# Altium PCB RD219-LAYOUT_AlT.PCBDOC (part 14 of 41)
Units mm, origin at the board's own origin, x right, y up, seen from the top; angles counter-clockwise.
Board outline 209.75 x 159.97 mm, 2 copper layers (TOP, BOTTOM), stack 0 mm thick; 398 components, 199 nets, 1469 pads, 0 vias.
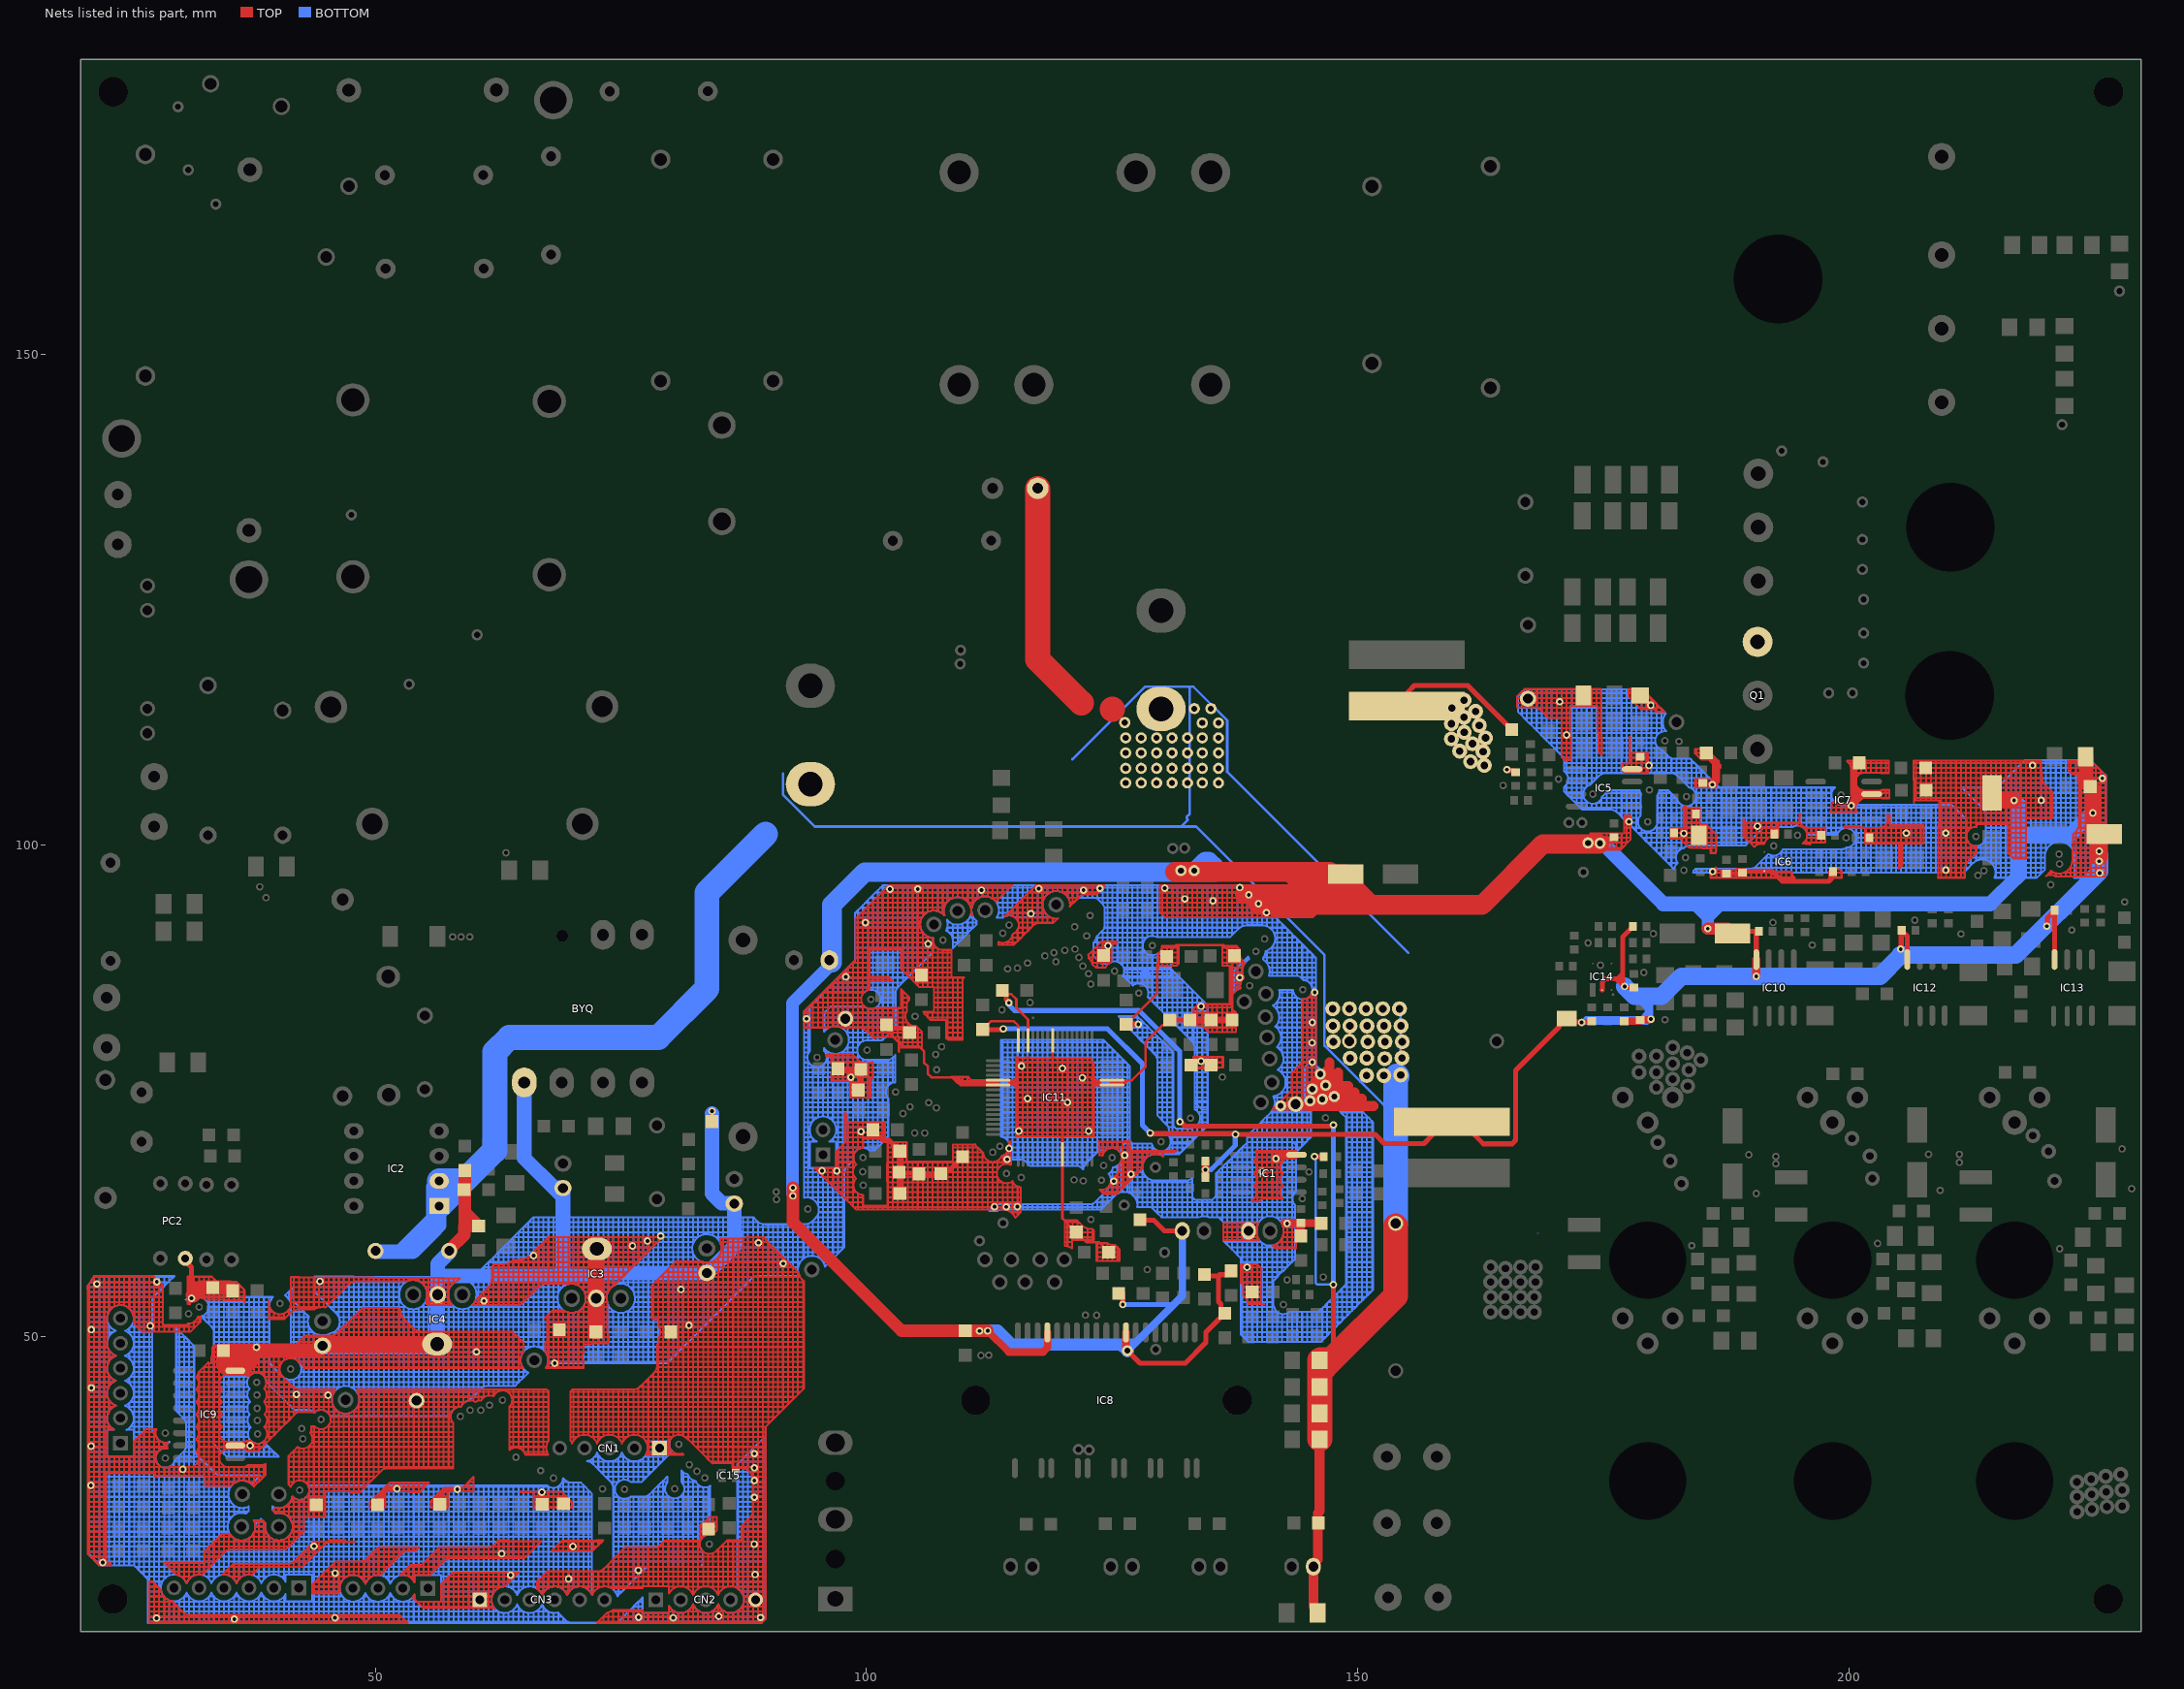
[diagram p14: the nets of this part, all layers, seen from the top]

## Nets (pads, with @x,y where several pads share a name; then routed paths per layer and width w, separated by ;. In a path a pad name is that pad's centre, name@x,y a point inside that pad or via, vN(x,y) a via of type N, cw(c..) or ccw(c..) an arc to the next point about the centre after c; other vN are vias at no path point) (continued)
GND: (continued)
  TOP w0.203: 113.345,67.931 ccw(c112.851,68.781) 113.684,68.26 ; 113.345,94.45 113.345,94.676 ; 113.345,94.45 113.571,94.676 ; 113.345,94.676 113.345,95.184 ; 113.345,94.676 113.571,94.676 ; 113.345,95.184 113.345,95.692 ; 113.345,95.184 113.853,95.184 ; 113.345,95.692 113.345,95.946 ; 113.345,95.692 113.853,95.692 ; 113.345,95.946 113.853,95.946 ; 113.454,90.104 113.454,89.885 113.853,89.885 ; 113.454,90.104 113.619,90.104 ; 113.454,90.104 113.454,90.163 ; 113.454,90.163 ccw(c113.863,91.056) 113.619,90.104 ; 113.571,94.676 113.853,94.958 ; 113.619,90.104 ccw(c113.863,91.056) 113.846,90.073 ccw(c113.863,91.056) 113.853,90.073 ; 113.684,68.26 113.853,68.26 ; 113.828,65.72 ccw(c114.245,66.61) 113.853,65.709 ; 113.853,62.932 113.853,63.18 ; 113.853,62.932 113.895,62.932 ; 113.853,63.18 113.853,63.688 ; 113.853,63.18 pad.@114.361,63.18 ; 113.853,63.688 113.853,64.196 ; 113.853,63.688 114.361,63.688 ; 113.853,64.196 113.853,64.704 ; 113.853,64.196 114.361,64.196 ; 113.853,64.704 113.853,65.212 ; 113.853,64.704 114.361,64.704 ; 113.853,65.212 114.361,65.212 ; 113.853,65.212 113.853,65.709 ; 113.853,65.709 ccw(c114.245,66.61) 114.361,65.634 ; 113.853,67.511 cw(c114.245,66.61) 114.361,67.586 ; 113.853,67.511 113.853,67.752 ; 113.853,67.752 pad.@114.361,67.752 ; 113.853,67.752 113.853,68.26 ; 113.853,68.26 pad.@114.361,68.26 ; 113.853,68.26 113.853,68.436 ; 113.853,68.436 ccw(c113.576,69.379) 114.346,68.768 ; 113.853,89.885 114.361,89.885 ; 113.853,89.885 113.853,90.073 ; 113.853,90.073 ccw(c113.863,91.056) 114.101,90.102 ccw(c113.863,91.056) 114.108,90.104 ; 113.853,94.958 113.853,95.184 ; 113.853,94.958 114.079,95.184 ; 113.853,95.184 113.853,95.692 ; 113.853,95.184 114.079,95.184 ; 113.853,95.692 113.853,95.946 ; 113.853,95.692 114.361,95.692 ; 113.853,95.946 114.361,95.946 ; 113.895,62.932 cw(c113.895,61.581) 114.361,62.85 ; 113.895,62.932 cw(c113.895,61.581) 114.361,62.85 ; 114.079,95.184 114.361,95.466 ; 114.108,90.104 ccw(c113.863,91.056) 114.355,90.205 ccw(c113.863,91.056) 114.361,90.208 ; 114.108,90.104 114.361,90.104 ; 114.346,68.768 ccw(c113.576,69.379) 114.361,68.788 ; 114.346,68.768 114.361,68.768 ; 114.361,62.85 cw(c113.895,61.581) 114.693,62.672 ; 114.361,62.85 cw(c113.895,61.581) 114.693,62.672 ; 114.361,62.85 pad.@114.361,63.18 ; pad.@114.361,63.18 114.869,63.18 ; pad.@114.361,63.18 114.361,63.688 ; 114.361,63.688 114.361,64.196 ; 114.361,63.688 114.869,63.688 ; 114.361,64.196 114.361,64.704 ; 114.361,64.196 114.869,64.196 ; 114.361,64.704 114.361,65.212 ; 114.361,64.704 114.869,64.704 ; 114.361,65.212 114.869,65.212 ; 114.361,65.212 114.361,65.634 ; 114.361,65.634 ccw(c114.245,66.61) 114.661,65.72 ; 114.361,67.586 cw(c114.245,66.61) 114.685,67.488 ; 114.361,67.586 pad.@114.361,67.752 ; pad.@114.361,67.752 114.685,67.752 ; pad.@114.361,67.752 pad.@114.361,68.26 ; pad.@114.361,68.26 114.685,68.26 ; pad.@114.361,68.26 114.361,68.768 ; 114.361,68.768 114.361,68.788 ; 114.361,68.768 114.685,68.768 ; 114.361,68.788 ccw(c113.576,69.379) pad.@114.553,69.276 ; 114.361,89.885 114.869,89.885 ; 114.361,89.885 114.361,90.104 ; 114.361,90.104 114.869,90.104 ; 114.361,90.104 114.361,90.208 ; 114.361,90.208 ccw(c113.863,91.056) 114.739,90.61 ccw(c113.863,91.056) 114.74,90.612 ; 114.361,95.466 114.361,95.692 ; 114.361,95.466 114.841,95.946 114.361,95.946 ; 114.361,95.692 114.361,95.946 ; 114.455,93.152 114.869,93.152 ; 114.455,93.152 114.869,93.566 ; 114.472,69.784 cw(c113.576,69.379) 114.559,69.379 cw(c113.576,69.379) pad.@114.553,69.276 ; 114.472,69.784 114.696,69.784 ; pad.@114.553,69.276 pad.@114.685,69.276 ; 114.661,65.72 ccw(c114.245,66.61) 114.842,65.83 ; 114.661,65.72 114.869,65.72 ; 114.682,75.88 cw(c114.487,76.606) 114.539,75.856 cw(c114.487,75.106) 114.869,75.753 ; 114.682,75.88 ccw(c114.487,76.606) 114.869,75.959 ; 114.682,75.88 114.869,75.88 ; 114.685,67.488 114.685,67.752 ; 114.685,67.752 114.685,68.26 ; 114.685,68.26 114.685,68.768 ; 114.685,68.768 pad.@114.685,69.276 ; pad.@114.685,69.276 114.685,69.656 cw(c115.437,69.656) 114.696,69.784 ; 114.693,62.672 cw(c113.895,61.581) 114.851,62.537 ccw(c113.895,61.581) 114.693,62.672 ; 114.693,62.672 114.869,62.672 ; 114.74,90.612 114.869,90.612 ; 114.842,65.83 ccw(c115.751,66.202) 114.869,65.769 ; 114.869,62.518 cw(c113.9,61.576) 115.117,62.164 ; 114.869,62.518 114.869,62.672 ; 114.869,62.672 114.869,63.18 ; 114.869,62.672 115.377,62.672 ; 114.869,63.18 114.869,63.688 ; 114.869,63.18 pad.@115.377,63.18 ; 114.869,63.688 114.869,64.196 ; 114.869,63.688 115.377,63.688 ; 114.869,64.196 114.869,64.704 ; 114.869,64.196 115.377,64.196 ; 114.869,64.704 114.869,65.212 ; 114.869,64.704 115.377,64.704 ; 114.869,65.212 114.869,65.72 ; 114.869,65.212 115.377,65.212 ; 114.869,65.72 114.895,65.72 ; 114.869,65.72 114.869,65.769 ; 114.869,65.769 ccw(c115.751,66.202) 114.895,65.72 ; 114.869,75.753 cw(c114.487,75.106) 115.028,75.628 cw(c114.487,75.106) 115.03,75.626 cw(c114.487,75.106) 115.189,75.375 cw(c114.487,75.106) 115.19,75.372 ; 114.869,75.753 114.869,75.88 ; 114.869,75.88 115.377,75.88 ; 114.869,75.88 114.869,75.959 ; 114.869,75.959 ccw(c114.487,76.606) 114.874,75.962 ccw(c114.487,76.606) 115.034,76.091 ccw(c114.487,76.606) 115.087,76.154 ccw(c114.487,76.606) 115.206,76.386 ccw(c114.487,76.606) 115.206,76.388 ; 114.869,89.885 115.016,89.885 115.236,90.104 ; 114.869,89.885 114.869,90.104 ; 114.869,90.104 114.869,90.612 ; 114.869,90.104 115.236,90.104 ; 114.869,90.612 115.377,90.612 ; 114.869,90.612 114.869,90.977 ; 114.869,90.977 ccw(c114.506,91.891) 115.111,91.116 ccw(c114.506,91.891) 115.116,91.12 ; 114.869,92.804 cw(c114.506,91.891) 115.137,92.644 ; 114.869,92.804 114.869,93.152 ; 114.869,93.152 114.869,93.566 ; 114.869,93.152 115.377,93.152 ; 114.869,93.566 114.963,93.66 ; 114.963,93.66 115.377,94.074 ; 114.963,93.66 115.377,93.66 ; 115.117,62.164 cw(c113.9,61.576) 115.144,62.106 ; 115.116,91.12 ccw(c114.506,91.891) 115.374,91.429 ccw(c114.506,91.891) 115.377,91.435 ; 115.116,91.12 115.377,91.12 ; 115.137,92.644 cw(c114.506,91.891) 115.374,92.352 cw(c114.506,91.891) 115.377,92.346 ; 115.137,92.644 115.377,92.644 ; 115.144,62.106 115.377,62.339 ; 115.17,78.42 cw(c114.487,78.106) 115.239,78.106 cw(c114.487,78.106) 115.213,77.912 ; 115.17,78.42 115.377,78.42 ; 115.19,75.372 cw(c114.487,75.106) 115.239,75.106 cw(c114.487,75.106) 115.199,74.864 ; 115.19,75.372 115.377,75.372 ; 115.199,73.848 115.377,73.848 ; 115.199,74.864 115.377,74.864 ; 115.201,73.34 115.377,73.34 ; 115.204,72.832 115.377,72.832 ; 115.206,72.324 115.377,72.324 ; 115.206,76.388 115.377,76.388 ; 115.209,71.816 115.377,71.816 ; 115.209,76.896 115.377,76.896 ; 115.211,71.308 115.377,71.308 ; 115.211,77.404 115.377,77.404 ; pad.@115.213,70.8 pad.@115.377,70.8 ; 115.213,77.912 115.377,77.912 ; 115.236,90.104 115.377,90.245 ; 115.377,62.339 115.377,62.672 ; 115.377,62.339 115.708,62.671 115.708,62.672 ; 115.377,62.672 pad.@115.377,63.18 ; 115.377,62.672 115.708,62.672 ; pad.@115.377,63.18 pad.@115.708,63.18 ; pad.@115.377,63.18 115.377,63.688 ; 115.377,63.688 115.377,64.196 ; 115.377,63.688 115.708,63.688 ; 115.377,64.196 115.377,64.704 ; 115.377,64.196 115.708,64.196 ; 115.377,64.704 115.377,65.212 ; 115.377,64.704 115.708,64.704 ; 115.377,65.212 115.708,65.212 ; 115.377,70.405 pad.@115.377,70.8 ; pad.@115.377,70.8 115.377,71.308 ; pad.@115.377,70.8 115.885,70.8 ; 115.377,71.308 115.377,71.816 ; 115.377,71.308 115.885,71.308 ; 115.377,71.816 115.377,72.324 ; 115.377,71.816 115.885,71.816 ; 115.377,72.324 115.885,72.324 ; 115.377,72.324 115.377,72.832 ; 115.377,72.832 115.885,72.832 ; 115.377,72.832 115.377,73.34 ; 115.377,73.34 115.885,73.34 ; 115.377,73.34 115.377,73.848 ; 115.377,73.848 115.885,73.848 ; 115.377,73.848 115.377,74.356 ; 115.377,74.356 115.885,74.356 ; 115.377,74.356 115.377,74.864 ; 115.377,74.864 115.885,74.864 ; 115.377,74.864 115.377,75.372 ; 115.377,75.372 115.377,75.88 ; 115.377,75.372 115.885,75.372 ; 115.377,75.88 115.885,75.88 ; 115.377,75.88 115.377,76.388 ; 115.377,76.388 115.377,76.896 ; 115.377,76.388 115.885,76.388 ; 115.377,76.896 115.377,77.404 ; 115.377,76.896 115.885,76.896 ; 115.377,77.404 pad.@115.885,77.404 ; 115.377,77.404 115.377,77.912 ; 115.377,77.912 115.377,78.42 ; 115.377,77.912 pad.@115.885,77.912 ; 115.377,90.245 115.377,90.612 ; 115.377,90.245 115.744,90.612 ; 115.377,90.612 115.377,91.12 ; 115.377,90.612 115.744,90.612 ; 115.377,91.12 115.885,91.12 ; 115.377,91.12 115.377,91.435 ; 115.377,91.435 ccw(c114.506,91.891) 115.453,91.628 ; 115.377,92.346 cw(c114.506,91.891) 115.458,92.136 ; 115.377,92.346 115.377,92.644 ; 115.377,92.644 115.377,93.152 ; 115.377,92.644 115.885,92.644 ; 115.377,93.152 115.377,93.66 ; 115.377,93.152 115.885,93.152 ; 115.377,93.66 115.377,94.074 ; 115.377,93.66 115.885,93.66 ; 115.377,94.074 115.471,94.168 ; 115.453,91.628 ccw(c114.506,91.891) 115.489,91.891 ccw(c114.506,91.891) 115.458,92.136 ; 115.453,91.628 115.885,91.628 ; 115.458,92.136 115.885,92.136 ; 115.471,94.168 115.885,94.582 ; 115.471,94.168 115.885,94.168 ; 115.708,62.672 pad.@115.708,63.18 ; pad.@115.708,63.18 115.708,63.688 ; 115.708,63.688 115.708,64.196 ; 115.708,64.196 115.708,64.704 ; 115.708,64.704 115.708,65.212 ; 115.708,65.212 115.708,65.221 ; 115.744,90.612 115.885,90.753 ; 115.885,70.406 115.885,70.8 ; 115.885,70.8 116.393,70.8 ; 115.885,70.8 115.885,71.308 ; 115.885,71.308 115.885,71.816 ; 115.885,71.308 116.393,71.308 ; 115.885,71.816 115.885,72.324 ; 115.885,71.816 116.393,71.816 ; 115.885,72.324 115.885,72.832 ; 115.885,72.324 116.393,72.324 ; 115.885,72.832 116.393,72.832 ; 115.885,72.832 115.885,73.34 ; 115.885,73.34 116.393,73.34 ; 115.885,73.34 115.885,73.848 ; 115.885,73.848 116.393,73.848 ; 115.885,73.848 115.885,74.356 ; 115.885,74.356 pad.@116.393,74.356 ; 115.885,74.356 115.885,74.864 ; 115.885,74.864 116.393,74.864 ; 115.885,74.864 115.885,75.372 ; 115.885,75.372 115.885,75.88 ; 115.885,75.372 116.393,75.372 ; 115.885,75.88 115.885,76.388 ; 115.885,75.88 116.393,75.88 ; 115.885,76.388 115.885,76.896 ; 115.885,76.388 116.393,76.388 ; 115.885,76.896 pad.@115.885,77.404 ; 115.885,76.896 116.393,76.896 ; pad.@115.885,77.404 116.393,77.404 ; pad.@115.885,77.404 pad.@115.885,77.912 ; pad.@115.885,77.912 116.393,77.912 ; pad.@115.885,77.912 115.885,78.306 ; 115.885,90.753 116.252,91.12 ; 115.885,90.753 115.885,91.12 ; 115.885,91.12 116.252,91.12 ; 115.885,91.12 115.885,91.628 ; 115.885,91.628 115.885,92.136 ; 115.885,91.628 116.393,91.628 ; 115.885,92.136 115.885,92.644 ; 115.885,92.136 116.393,92.136 ; 115.885,92.644 115.885,93.152 ; 115.885,92.644 116.393,92.644 ; 115.885,93.152 115.885,93.66 ; 115.885,93.152 pad.@116.393,93.152 ; 115.885,93.66 115.885,94.168 ; 115.885,93.66 116.393,93.66 ; 115.885,94.168 115.885,94.582 ; 115.885,94.168 116.393,94.168 ; 115.885,94.582 115.979,94.676 ; 115.979,94.676 116.393,94.676 ; 115.979,94.676 116.393,95.09 ; 116.252,91.12 116.393,91.261 ; 116.393,70.406 116.393,70.8 ; 116.393,70.8 116.393,71.308 ; 116.393,70.8 116.901,70.8 ; 116.393,71.308 116.393,71.816 ; 116.393,71.308 116.901,71.308 ; 116.393,71.816 116.393,72.324 ; 116.393,71.816 116.901,71.816 ; 116.393,72.324 116.393,72.832 ; 116.393,72.324 116.901,72.324 ; 116.393,72.832 116.901,72.832 ; 116.393,72.832 116.393,73.34 ; 116.393,73.34 116.901,73.34 ; 116.393,73.34 116.393,73.848 ; 116.393,73.848 116.901,73.848 ; 116.393,73.848 pad.@116.393,74.356 ; pad.@116.393,74.356 116.393,74.864 ; pad.@116.393,74.356 116.901,74.356 ; 116.393,74.864 116.901,74.864 ; 116.393,74.864 116.393,75.372 ; 116.393,75.372 116.393,75.88 ; 116.393,75.372 116.901,75.372 ; 116.393,75.88 116.393,76.388 ; 116.393,75.88 116.901,75.88 ; 116.393,76.388 116.393,76.896 ; 116.393,76.388 116.901,76.388 ; 116.393,76.896 116.393,77.404 ; 116.393,76.896 116.901,76.896 ; 116.393,77.404 116.393,77.912 ; 116.393,77.404 116.901,77.404 ; 116.393,77.912 116.393,78.42 ; 116.393,77.912 116.901,77.912 ; 116.393,91.261 116.76,91.628 ; 116.393,91.261 116.393,91.628 ; 116.393,91.628 116.76,91.628 ; 116.393,91.628 116.393,92.136 ; 116.393,92.136 116.901,92.136 ; 116.393,92.136 116.393,92.644 ; 116.393,92.644 116.901,92.644 ; 116.393,92.644 pad.@116.393,93.152 ; pad.@116.393,93.152 116.393,93.66 ; pad.@116.393,93.152 pad.@116.901,93.152 ; 116.393,93.66 116.393,94.168 ; 116.393,93.66 116.901,93.66 ; 116.393,94.168 116.393,94.676 ; 116.393,94.168 116.901,94.168 ; 116.393,94.676 116.393,95.09 ; 116.393,94.676 116.901,94.676 ; 116.393,95.09 116.487,95.184 ; 116.487,95.184 116.995,95.692 ; 116.487,95.184 116.901,95.184 ; 116.76,91.628 116.901,91.769 ; 116.901,70.407 116.901,70.8 ; 116.901,70.8 116.901,71.308 ; 116.901,70.8 117.409,70.8 ; 116.901,71.308 116.901,71.816 ; 116.901,71.308 117.409,71.308 ; 116.901,71.816 116.901,72.324 ; 116.901,71.816 117.409,71.816 ; 116.901,72.324 116.901,72.832 ; 116.901,72.324 117.409,72.324 ; 116.901,72.832 116.901,73.34 ; 116.901,72.832 117.409,72.832 ; 116.901,73.34 116.901,73.848 ; 116.901,73.34 117.409,73.34 ; 116.901,73.848 116.901,74.356 ; 116.901,73.848 117.409,73.848 ; 116.901,74.356 116.901,74.864 ; 116.901,74.356 117.409,74.356 ; 116.901,74.864 116.901,75.372 ; 116.901,74.864 117.409,74.864 ; 116.901,75.372 116.901,75.88 ; 116.901,75.372 117.409,75.372 ; 116.901,75.88 116.901,76.388 ; 116.901,75.88 117.409,75.88 ; 116.901,76.388 116.901,76.896 ; 116.901,76.388 117.409,76.388 ; 116.901,76.896 116.901,77.404 ; 116.901,76.896 117.409,76.896 ; 116.901,77.404 116.901,77.912 ; 116.901,77.404 117.409,77.404 ; 116.901,77.912 117.409,77.912 ; 116.901,77.912 116.901,78.305 ; 116.901,91.769 116.901,92.136 ; 116.901,91.769 117.021,91.889 ; 116.901,92.136 116.901,92.644 ; 116.901,92.136 117.409,92.136 ; 116.901,92.644 117.409,92.644 ; 116.901,92.644 pad.@116.901,93.152 ; pad.@116.901,93.152 116.901,93.66 ; pad.@116.901,93.152 117.409,93.152 ; 116.901,93.66 116.901,94.168 ; 116.901,93.66 117.409,93.66 ; 116.901,94.168 116.901,94.676 ; 116.901,94.168 117.409,94.168 ; 116.901,94.676 116.901,95.184 ; 116.901,94.676 117.409,94.676 ; 116.901,95.184 117.409,95.184 ; 116.995,95.692 pad.@117.409,95.692 ; 116.995,95.692 117.249,95.946 pad.@117.409,95.946 ; 117.021,91.889 cw(c117.536,91.374) 117.409,92.091 ; 117.021,91.889 cw(c117.536,91.374) 117.409,92.091 ; 117.409,70.407 117.409,70.8 ; 117.409,70.8 117.409,71.308 ; 117.409,70.8 117.917,70.8 ; 117.409,71.308 117.409,71.816 ; 117.409,71.308 117.917,71.308 ; 117.409,71.816 117.409,72.324 ; 117.409,71.816 117.917,71.816 ; 117.409,72.324 117.409,72.832 ; 117.409,72.324 117.917,72.324 ; 117.409,72.832 117.409,73.34 ; 117.409,72.832 117.917,72.832 ; 117.409,73.34 117.409,73.848 ; 117.409,73.34 117.917,73.34 ; 117.409,73.848 117.409,74.356 ; 117.409,73.848 117.917,73.848 ; 117.409,74.356 117.409,74.864 ; 117.409,74.356 117.917,74.356 ; 117.409,74.864 117.409,75.372 ; 117.409,74.864 117.917,74.864 ; 117.409,75.372 117.409,75.88 ; 117.409,75.372 117.917,75.372 ; 117.409,75.88 117.409,76.388 ; 117.409,75.88 117.917,75.88 ; 117.409,76.388 117.409,76.896 ; 117.409,76.388 117.917,76.388 ; 117.409,76.896 117.409,77.404 ; 117.409,76.896 117.917,76.896 ; 117.409,77.404 117.409,77.912 ; 117.409,77.404 117.917,77.404 ; 117.409,77.912 117.917,77.912 ; 117.409,77.912 117.409,78.305 ; 117.409,92.091 cw(c117.536,91.374) 117.536,92.103 ; 117.409,92.091 cw(c117.536,91.374) 117.536,92.103 ; 117.409,92.091 117.409,92.136 ; 117.409,92.136 117.409,92.644 ; 117.409,92.136 117.917,92.136 ; 117.409,92.644 117.409,93.152 ; 117.409,92.644 117.917,92.644 ; 117.409,93.152 117.409,93.66 ; 117.409,93.152 117.917,93.152 ; 117.409,93.66 117.917,93.66 ; 117.409,93.66 117.409,94.168 ; 117.409,94.168 117.917,94.168 ; 117.409,94.168 117.409,94.676 ; 117.409,94.676 117.409,95.184 ; 117.409,94.676 117.917,94.676 ; 117.409,95.184 117.917,95.184 ; 117.409,95.184 pad.@117.409,95.692 ; pad.@117.409,95.692 pad.@117.409,95.946 ; pad.@117.409,95.692 117.917,95.692 ; pad.@117.409,95.946 117.917,95.946 ; 117.536,92.103 117.917,92.103 ; 117.917,70.407 117.917,70.8 ; 117.917,70.8 117.917,71.308 ; 117.917,70.8 118.425,70.8 ; 117.917,71.308 117.917,71.816 ; 117.917,71.308 118.425,71.308 ; 117.917,71.816 117.917,72.324 ; 117.917,71.816 118.425,71.816 ; 117.917,72.324 117.917,72.832 ; 117.917,72.324 118.425,72.324 ; 117.917,72.832 117.917,73.34 ; 117.917,72.832 118.425,72.832 ; 117.917,73.34 117.917,73.848 ; 117.917,73.34 118.425,73.34 ; 117.917,73.848 117.917,74.356 ; 117.917,73.848 118.425,73.848 ; 117.917,74.356 117.917,74.864 ; 117.917,74.356 118.425,74.356 ; 117.917,74.864 117.917,75.372 ; 117.917,74.864 118.425,74.864 ; 117.917,75.372 117.917,75.88 ; 117.917,75.372 118.425,75.372 ; 117.917,75.88 117.917,76.388 ; 117.917,75.88 118.425,75.88 ; 117.917,76.388 117.917,76.896 ; 117.917,76.388 118.425,76.388 ; 117.917,76.896 117.917,77.404 ; 117.917,76.896 118.425,76.896 ; 117.917,77.404 117.917,77.912 ; 117.917,77.404 118.425,77.404 ; 117.917,77.912 118.425,77.912 ; 117.917,77.912 117.917,78.305 ; 117.917,92.103 117.917,92.136 ; 117.917,92.103 118.425,92.103 ; 117.917,92.136 117.917,92.644 ; 117.917,92.136 118.425,92.136 ; 117.917,92.644 117.917,93.152 ; 117.917,92.644 118.425,92.644 ; 117.917,93.152 117.917,93.66 ; 117.917,93.152 118.165,93.152 ; 117.917,93.66 117.944,93.66 ; 117.917,94.067 cw(c119.314,93.954) 117.918,94.076 cw(c119.314,93.954) 117.929,94.168 ; 117.917,94.067 117.917,94.168 ; 117.917,94.168 117.917,94.676 ; 117.917,94.168 117.929,94.168 ; 117.917,94.676 117.917,95.184 ; 117.917,94.676 118.113,94.676 ; 117.917,95.184 118.425,95.184 ; 117.917,95.184 117.917,95.692 ; 117.917,95.692 117.917,95.946 ; 117.917,95.692 118.425,95.692 ; 117.917,95.946 118.425,95.946 ; 117.929,94.168 cw(c119.314,93.954) 118.113,94.676 ; 117.944,93.66 ccw(c119.314,93.954) 118.165,93.152 ; 118.113,94.676 cw(c119.314,93.954) 118.425,95.038 ; 118.165,93.152 ccw(c119.314,93.954) 118.166,93.15 ccw(c119.314,93.954) 118.425,92.87 ; 118.425,70.8 118.933,70.8 ; 118.425,70.8 118.425,71.308 ; 118.425,71.308 118.933,71.308 ; 118.425,71.308 118.425,71.816 ; 118.425,71.816 118.933,71.816 ; 118.425,71.816 118.425,72.324 ; 118.425,72.324 118.933,72.324 ; 118.425,72.324 118.425,72.832 ; 118.425,72.832 118.933,72.832 ; 118.425,72.832 118.425,73.34 ; 118.425,73.34 118.933,73.34 ; 118.425,73.34 118.425,73.848 ; 118.425,73.848 118.933,73.848 ; 118.425,73.848 118.425,74.356 ; 118.425,74.356 118.933,74.356 ; 118.425,74.356 118.425,74.864 ; 118.425,74.864 118.933,74.864 ; 118.425,74.864 118.425,75.372 ; 118.425,75.372 118.425,75.88 ; 118.425,75.372 118.933,75.372 ; 118.425,75.88 118.933,75.88 ; 118.425,75.88 118.425,76.388 ; 118.425,76.388 118.425,76.896 ; 118.425,76.388 118.933,76.388 ; 118.425,76.896 118.933,76.896 ; 118.425,76.896 118.425,77.404 ; 118.425,77.404 118.933,77.404 ; 118.425,77.404 118.425,77.912 ; 118.425,77.912 118.933,77.912 ; 118.425,77.912 118.425,78.304 ; 118.425,92.103 118.933,92.103 ; 118.425,92.103 118.425,92.136 ; 118.425,92.136 118.933,92.136 ; 118.425,92.136 118.425,92.644 ; 118.425,92.644 118.816,92.644 ; 118.425,92.644 118.425,92.87 ; 118.425,92.87 ccw(c119.314,93.954) 118.432,92.865 ccw(c119.314,93.954) 118.816,92.644 ; 118.425,95.038 cw(c119.314,93.954) 118.635,95.18 cw(c119.314,93.954) 118.642,95.184 ; 118.425,95.038 118.425,95.184 ; 118.425,95.184 118.425,95.692 ; 118.425,95.184 118.642,95.184 ; 118.425,95.692 118.425,95.946 ; 118.425,95.692 118.933,95.692 ; 118.425,95.946 118.933,95.946 ; 118.642,95.184 cw(c119.314,93.954) 118.928,95.301 cw(c119.314,93.954) 118.933,95.303 ; 118.816,92.644 ccw(c119.314,93.954) 118.933,92.605 ; 118.933,70.408 118.933,70.8 ; 118.933,70.8 119.441,70.8 ; 118.933,70.8 118.933,71.308 ; 118.933,71.308 118.933,71.816 ; 118.933,71.308 119.441,71.308 ; 118.933,71.816 119.441,71.816 ; 118.933,71.816 118.933,72.324 ; 118.933,72.324 118.933,72.832 ; 118.933,72.324 119.441,72.324 ; 118.933,72.832 119.441,72.832 ; 118.933,72.832 118.933,73.34 ; 118.933,73.34 119.441,73.34 ; 118.933,73.34 118.933,73.848 ; 118.933,73.848 119.441,73.848 ; 118.933,73.848 118.933,74.356 ; 118.933,74.356 119.441,74.356 ; 118.933,74.356 118.933,74.864 ; 118.933,74.864 119.441,74.864 ; 118.933,74.864 118.933,75.372 ; 118.933,75.372 118.933,75.88 ; 118.933,75.372 119.441,75.372 ; 118.933,75.88 119.441,75.88 ; 118.933,75.88 118.933,76.388 ; 118.933,76.388 118.933,76.896 ; 118.933,76.388 119.441,76.388 ; 118.933,76.896 119.441,76.896 ; 118.933,76.896 118.933,77.404 ; 118.933,77.404 118.933,77.912 ; 118.933,77.404 119.441,77.404 ; 118.933,77.912 118.937,77.912 119.441,77.912 ; 118.933,77.912 118.933,78.42 ; 118.933,92.103 118.933,92.136 ; 118.933,92.103 119.012,92.103 119.471,92.561 ; 118.933,92.136 118.933,92.605 ; 118.933,92.605 ccw(c119.314,93.954) 119.471,92.561 ; 118.933,95.303 cw(c119.314,93.954) 119.436,95.35 cw(c119.314,93.954) 119.441,95.35 ; 118.933,95.303 118.933,95.692 ; 118.933,95.692 118.933,95.946 ; 118.933,95.692 119.441,95.692 ; 118.933,95.946 119.441,95.946 ; 119.441,70.8 119.441,71.308 ; 119.441,70.8 119.937,70.8 119.949,70.8 ; 119.441,71.308 119.441,71.816 ; 119.441,71.308 119.937,71.308 119.949,71.308 ; 119.441,71.816 119.441,72.324 ; 119.441,71.816 119.937,71.816 119.949,71.816 ; 119.441,72.324 119.441,72.832 ; 119.441,72.324 119.937,72.324 119.949,72.324 ; 119.441,72.832 119.441,73.34 ; 119.441,72.832 119.937,72.832 119.949,72.832 ; 119.441,73.34 119.441,73.848 ; 119.441,73.34 119.937,73.34 119.949,73.34 ; 119.441,73.848 119.949,73.848 ; 119.441,73.848 119.441,74.356 ; 119.441,74.356 119.949,74.356 ; 119.441,74.356 119.441,74.864 ; 119.441,74.864 119.949,74.864 ; 119.441,74.864 119.441,75.372 ; 119.441,75.372 119.441,75.88 ; 119.441,75.372 119.949,75.372 ; 119.441,75.88 119.949,75.88 ; 119.441,75.88 119.441,76.388 ; 119.441,76.388 119.441,76.896 ; 119.441,76.388 119.949,76.388 ; 119.441,76.896 119.441,77.404 ; 119.441,76.896 119.949,76.896 ; 119.441,77.404 119.441,77.912 ; 119.441,77.404 pad.@119.949,77.404 ; 119.441,77.912 119.949,77.912 ; 119.441,77.912 119.441,78.304 ; 119.441,95.35 cw(c119.314,93.954) 119.949,95.204 ; 119.441,95.35 119.441,95.692 ; 119.441,95.692 119.949,95.692 ; 119.441,95.692 119.441,95.946 ; 119.441,95.946 119.949,95.946 ; 119.838,70.292 119.937,70.292 119.949,70.292 ; 119.949,70.228 cw(c120.437,69.656) 120.037,70.292 ; 119.949,70.228 119.949,70.292 ; 119.949,70.292 119.949,70.8 ; 119.949,70.292 120.037,70.292 ; 119.949,70.8 119.949,71.308 ; 119.949,70.8 120.457,70.8 ; 119.949,71.308 119.949,71.816 ; 119.949,71.308 120.457,71.308 ; 119.949,71.816 119.949,72.324 ; 119.949,71.816 120.457,71.816 ; 119.949,72.324 119.949,72.832 ; 119.949,72.324 120.457,72.324 ; 119.949,72.832 120.457,72.832 ; 119.949,72.832 119.949,73.34 ; 119.949,73.34 120.457,73.34 ; 119.949,73.34 119.949,73.848 ; 119.949,73.848 pad.@120.457,73.848 ; 119.949,73.848 119.949,74.356 ; 119.949,74.356 120.457,74.356 ; 119.949,74.356 119.949,74.864 ; 119.949,74.864 120.457,74.864 ; 119.949,74.864 119.949,75.372 ; 119.949,75.372 119.949,75.88 ; 119.949,75.372 120.457,75.372 ; 119.949,75.88 120.457,75.88 ; 119.949,75.88 119.949,76.388 ; 119.949,76.388 119.949,76.896 ; 119.949,76.388 120.457,76.388 ; 119.949,76.896 120.457,76.896 ; 119.949,76.896 pad.@119.949,77.404 ; pad.@119.949,77.404 119.949,77.912 ; pad.@119.949,77.404 120.457,77.404 ; 119.949,77.912 120.457,77.912 ; 119.949,77.912 119.949,78.304 ; 119.949,95.204 cw(c119.314,93.954) 119.986,95.184 ; 119.949,95.204 119.949,95.692 ; 119.949,95.692 120.457,95.692 ; 119.949,95.692 119.949,95.946 ; 119.949,95.946 120.457,95.946 ; 119.986,95.184 cw(c119.314,93.954) 120.457,94.765 ; 119.986,95.184 120.457,95.184 ; 120.037,70.292 cw(c120.437,69.656) 120.457,70.407 ; 120.166,59.624 120.457,59.624 ; 120.166,59.624 120.166,60.132 ; 120.166,60.132 120.166,60.64 ; 120.166,60.132 120.457,60.132 ; 120.166,60.64 120.166,61.148 ; 120.166,60.64 120.457,60.64 ; 120.166,61.148 120.166,61.656 ; 120.166,61.148 120.457,61.148 ; 120.166,61.656 120.166,61.82 120.166,61.878 120.457,61.878 ; 120.166,61.656 120.33,61.656 120.457,61.656 ; 120.457,59.207 cw(c120.121,57.846) 120.46,59.206 cw(c120.121,57.846) 120.714,59.116 ; 120.457,59.207 120.457,59.624 ; 120.457,59.624 120.457,60.132 ; 120.457,59.624 120.907,59.624 ; 120.457,60.132 120.457,60.64 ; 120.457,60.132 C64.2@120.965,60.132 ; 120.457,60.64 120.457,61.148 ; 120.457,60.64 C64.2@120.965,60.64 ; 120.457,61.148 120.457,61.529 120.457,61.656 ; 120.457,61.148 120.838,61.148 C64.2@120.965,61.148 ; 120.457,61.656 120.457,61.878 ; 120.457,61.656 120.965,61.656 ; 120.457,61.878 120.965,61.878 ; 120.457,70.407 120.457,70.8 ; 120.457,70.8 120.457,71.308 ; 120.457,70.8 120.965,70.8 ; 120.457,71.308 120.457,71.816 ; 120.457,71.308 120.965,71.308 ; 120.457,71.816 120.457,72.324 ; 120.457,71.816 120.965,71.816 ; 120.457,72.324 120.457,72.832 ; 120.457,72.324 120.965,72.324 ; 120.457,72.832 120.457,73.34 ; 120.457,72.832 120.965,72.832 ; 120.457,73.34 pad.@120.457,73.848 ; 120.457,73.34 120.965,73.34 ; pad.@120.457,73.848 120.457,74.356 ; pad.@120.457,73.848 120.965,73.848 ; 120.457,74.356 120.457,74.864 ; 120.457,74.356 120.965,74.356 ; 120.457,74.864 120.457,75.372 ; 120.457,74.864 120.965,74.864 ; 120.457,75.372 120.457,75.88 ; 120.457,75.372 120.965,75.372 ; 120.457,75.88 120.457,76.388 ; 120.457,75.88 120.965,75.88 ; 120.457,76.388 120.457,76.896 ; 120.457,76.388 120.965,76.388 ; 120.457,76.896 120.457,77.404 ; 120.457,76.896 120.965,76.896 ; 120.457,77.404 120.457,77.912 ; 120.457,77.404 120.965,77.404 ; 120.457,77.912 120.965,77.912 ; 120.457,77.912 120.457,78.305 ; 120.457,94.765 cw(c119.314,93.954) 120.515,94.676 ; 120.457,94.765 120.457,95.184 ; 120.457,95.184 120.457,95.692 ; 120.457,95.184 120.965,95.184 ; 120.457,95.692 120.965,95.692 ; 120.457,95.692 120.457,95.946 ; 120.457,95.946 120.965,95.946 ; 120.515,94.676 cw(c119.314,93.954) 120.698,94.173 cw(c119.314,93.954) 120.699,94.168 ; 120.515,94.676 120.965,94.676 ; 120.699,94.168 120.965,94.168 ; 120.714,59.116 120.907,59.116 ; 120.907,59.116 120.907,59.624 ; 120.907,59.624 120.907,59.86 120.965,59.86 ; 120.965,59.86 121.473,59.86 ; 120.965,59.86 C64.2@120.965,60.132 ; C64.2@120.965,60.132 C64.2@120.965,60.64 ; C64.2@120.965,60.132 C64.2@121.473,60.132 ; C64.2@120.965,60.64 C64.2@121.346,60.64 C64.2@121.473,60.64 ; C64.2@120.965,60.64 120.965,61.021 C64.2@120.965,61.148 ; C64.2@120.965,61.148 120.965,61.656 ; C64.2@120.965,61.148 C64.2@121.473,61.148 ; 120.965,61.656 121.473,61.656 ; 120.965,61.656 120.965,61.878 ; 120.965,61.878 121.388,61.878 121.473,61.792 ; 120.965,70.407 120.965,70.8 ; 120.965,70.8 120.965,71.308 ; 120.965,70.8 121.473,70.8 ; 120.965,71.308 120.965,71.816 ; 120.965,71.308 121.473,71.308 ; 120.965,71.816 120.965,72.324 ; 120.965,71.816 121.473,71.816 ; 120.965,72.324 120.965,72.832 ; 120.965,72.324 121.473,72.324 ; 120.965,72.832 120.965,73.34 ; 120.965,72.832 121.473,72.832 ; 120.965,73.34 120.965,73.848 ; 120.965,73.34 121.473,73.34 ; 120.965,73.848 120.965,74.356 ; 120.965,73.848 121.473,73.848 ; 120.965,74.356 120.965,74.864 ; 120.965,74.356 121.473,74.356 ; 120.965,74.864 120.965,75.372 ; 120.965,74.864 121.473,74.864 ; 120.965,75.372 120.965,75.88 ; 120.965,75.372 121.473,75.372 ; 120.965,75.88 120.965,76.388 ; 120.965,75.88 121.473,75.88 ; 120.965,76.388 120.965,76.896 ; 120.965,76.388 121.473,76.388 ; 120.965,76.896 120.965,77.404 ; 120.965,76.896 121.473,76.896 ; 120.965,77.404 120.965,77.912 ; 120.965,77.404 121.473,77.404 ; 120.965,77.912 121.473,77.912 ; 120.965,77.912 120.965,78.305 ; 120.965,94.055 120.965,94.168 ; 120.965,94.055 121.078,94.168 ; 120.965,94.168 120.965,94.676 ; 120.965,94.168 121.078,94.168 ; 120.965,94.676 121.473,94.676 ; 120.965,94.676 120.965,95.184 ; 120.965,95.184 121.473,95.184 ; 120.965,95.184 120.965,95.692 ; 120.965,95.692 121.473,95.692 ; 120.965,95.692 120.965,95.946 ; 120.965,95.946 121.473,95.946 ; 121.078,94.168 121.473,94.563 ; 121.473,59.86 121.981,59.86 ; 121.473,59.86 C64.2@121.473,60.132 ; C64.2@121.473,60.132 121.473,60.513 C64.2@121.473,60.64 ; C64.2@121.473,60.132 121.854,60.132 C64.2@121.981,60.132 ; C64.2@121.473,60.64 C64.2@121.981,60.64 ; C64.2@121.473,60.64 C64.2@121.473,61.148 ; C64.2@121.473,61.148 121.473,61.656 ; C64.2@121.473,61.148 C64.2@121.981,61.148 ; 121.473,61.656 121.609,61.656 ; 121.473,61.656 121.473,61.792 ; 121.473,61.792 121.609,61.656 ; 121.473,70.407 121.473,70.8 ; 121.473,70.8 121.473,71.308 ; 121.473,70.8 121.981,70.8 ; 121.473,71.308 121.473,71.816 ; 121.473,71.308 121.981,71.308 ; 121.473,71.816 121.473,72.324 ; 121.473,71.816 121.981,71.816 ; 121.473,72.324 121.473,72.832 ; 121.473,72.324 121.981,72.324 ; 121.473,72.832 121.473,73.34 ; 121.473,72.832 121.981,72.832 ; 121.473,73.34 121.473,73.848 ; 121.473,73.34 121.981,73.34 ; 121.473,73.848 121.473,74.356 ; 121.473,73.848 121.981,73.848 ; 121.473,74.356 121.473,74.864 ; 121.473,74.356 121.981,74.356 ; 121.473,74.864 121.473,75.372 ; 121.473,74.864 121.981,74.864 ; 121.473,75.372 121.473,75.88 ; 121.473,75.372 121.981,75.372 ; 121.473,75.88 121.473,76.388 ; 121.473,75.88 121.981,75.88 ; 121.473,76.388 121.473,76.896 ; 121.473,76.388 pad.@121.981,76.388 ; 121.473,76.896 121.473,77.404 ; 121.473,76.896 121.981,76.896 ; 121.473,77.404 121.473,77.912 ; 121.473,77.404 121.981,77.404 ; 121.473,77.912 121.981,77.912 ; 121.473,77.912 121.473,78.305 ; 121.473,94.563 121.473,94.676 ; 121.473,94.563 121.586,94.676 ; 121.473,94.676 121.473,95.184 ; 121.473,94.676 121.586,94.676 ; 121.473,95.184 121.473,95.692 ; 121.473,95.184 pad.@121.981,95.184 ; 121.473,95.692 121.473,95.946 ; 121.473,95.692 pad.@121.981,95.692 ; 121.473,95.946 121.981,95.946 ; 121.586,94.676 121.717,94.807 ; 121.609,61.656 121.97,61.295 ; 121.717,94.807 cw(c122.232,94.292) 121.981,94.976 ; 121.717,94.807 cw(c122.232,94.292) 121.981,94.976 ; 121.97,61.295 ccw(c122.575,61.9) C64.2@121.981,61.284 ; 121.97,61.295 ccw(c122.575,61.9) C64.2@121.981,61.284 ; 121.981,59.86 121.981,60.005 C64.2@121.981,60.132 ; 121.981,59.86 122.126,59.86 122.489,59.86 ; C64.2@121.981,60.132 122.489,60.132 ; C64.2@121.981,60.132 C64.2@121.981,60.64 ; C64.2@121.981,60.64 122.489,60.64 ; C64.2@121.981,60.64 C64.2@121.981,61.148 ; C64.2@121.981,61.148 C64.2@121.981,61.284 ; C64.2@121.981,61.148 122.167,61.148 ; C64.2@121.981,61.284 ccw(c122.575,61.9) 122.167,61.148 ; C64.2@121.981,61.284 ccw(c122.575,61.9) 122.167,61.148 ; 121.981,70.406 121.981,70.8 ; 121.981,70.8 pad.@122.489,70.8 ; 121.981,70.8 121.981,71.308 ; 121.981,71.308 122.489,71.308 ; 121.981,71.308 121.981,71.816 ; 121.981,71.816 122.489,71.816 ; 121.981,71.816 121.981,72.324 ; 121.981,72.324 122.489,72.324 ; 121.981,72.324 121.981,72.832 ; 121.981,72.832 122.489,72.832 ; 121.981,72.832 121.981,73.34 ; 121.981,73.34 122.489,73.34 ; 121.981,73.34 121.981,73.848 ; 121.981,73.848 122.489,73.848 ; 121.981,73.848 121.981,74.356 ; 121.981,74.356 122.489,74.356 ; 121.981,74.356 121.981,74.864 ; 121.981,74.864 122.489,74.864 ; 121.981,74.864 121.981,75.372 ; 121.981,75.372 121.981,75.88 ; 121.981,75.372 122.489,75.372 ; 121.981,75.88 122.489,75.88 ; 121.981,75.88 pad.@121.981,76.388 ; pad.@121.981,76.388 121.981,76.896 ; pad.@121.981,76.388 122.489,76.388 ; 121.981,76.896 122.489,76.896 ; 121.981,76.896 121.981,77.404 ; 121.981,77.404 122.489,77.404 ; 121.981,77.404 121.981,77.912 ; 121.981,77.912 122.489,77.912 ; 121.981,77.912 121.981,78.306 ; 121.981,94.976 cw(c122.232,94.292) 122.232,95.021 ; 121.981,94.976 cw(c122.232,94.292) 122.232,95.021 ; 121.981,94.976 pad.@121.981,95.184 ; pad.@121.981,95.184 122.489,95.184 ; pad.@121.981,95.184 pad.@121.981,95.692 ; pad.@121.981,95.692 121.981,95.946 ; pad.@121.981,95.692 122.489,95.692 ; 121.981,95.946 122.489,95.946 ; 122.167,61.148 ccw(c122.575,61.9) 122.173,61.145 ; 122.167,61.148 ccw(c122.575,61.9) 122.173,61.145 ; 122.173,61.145 ccw(c122.575,61.9) 122.368,61.07 cw(c122.575,61.9) 122.173,61.145 ; 122.232,95.021 122.489,95.021 ; 122.489,59.86 122.997,59.86 ; 122.489,59.86 122.489,60.132 ; 122.489,60.132 122.489,60.64 ; 122.489,60.132 122.997,60.132 ; 122.489,60.64 122.997,60.64 ; 122.489,60.64 122.489,61.015 ; 122.489,61.015 ccw(c122.835,61.935) 122.778,60.954 ; 122.489,70.406 pad.@122.489,70.8 ; pad.@122.489,70.8 122.489,71.308 ; pad.@122.489,70.8 122.997,70.8 ; 122.489,71.308 122.489,71.816 ; 122.489,71.308 122.997,71.308 ; 122.489,71.816 122.489,72.324 ; 122.489,71.816 122.997,71.816 ; 122.489,72.324 122.997,72.324 ; 122.489,72.324 122.489,72.832 ; 122.489,72.832 122.997,72.832 ; 122.489,72.832 122.489,73.34 ; 122.489,73.34 122.997,73.34 ; 122.489,73.34 122.489,73.848 ; 122.489,73.848 122.997,73.848 ; 122.489,73.848 122.489,74.356 ; 122.489,74.356 122.997,74.356 ; 122.489,74.356 122.489,74.864 ; 122.489,74.864 122.997,74.864 ; 122.489,74.864 122.489,75.372 ; 122.489,75.372 122.489,75.88 ; 122.489,75.372 122.997,75.372 ; 122.489,75.88 122.997,75.88 ; 122.489,75.88 122.489,76.388 ; 122.489,76.388 122.489,76.896 ; 122.489,76.388 122.997,76.388 ; 122.489,76.896 122.489,77.404 ; 122.489,76.896 122.997,76.896 ; 122.489,77.404 122.489,77.912 ; 122.489,77.404 122.997,77.404 ; 122.489,77.912 122.997,77.912 ; 122.489,77.912 122.489,78.306 ; 122.489,95.021 122.489,95.184 ; 122.489,95.021 122.997,95.021 ; 122.489,95.184 122.997,95.184 ; 122.489,95.184 122.489,95.692 ; 122.489,95.692 122.489,95.946 ; 122.489,95.692 122.997,95.692 ; 122.489,95.946 122.997,95.946 ; 122.571,88.864 cw(c121.624,88.601) 122.606,88.58 ; 122.571,88.864 ccw(c122.132,89.446) 122.647,88.93 ; 122.571,88.864 ccw(c122.132,89.446) 122.647,88.93 ; 122.606,88.58 122.997,88.58 ; 122.647,88.93 123.914,90.198 124.013,90.198 ; 122.778,60.954 cw(c122.881,61.803) 122.777,60.954 ccw(c122.881,61.803) 122.778,60.954 ; 122.778,60.954 ccw(c122.881,61.803) 122.881,60.947 ; 122.778,60.954 ccw(c122.881,61.803) 122.881,60.947 ; 122.881,60.947 122.997,60.947 ; 122.906,78.305 cw(c123.632,78.361) 122.905,78.31 ccw(c123.632,78.361) 122.906,78.305 ; 122.906,78.305 ccw(c123.632,78.361) 122.997,78.004 ; 122.906,78.305 ccw(c123.632,78.361) 122.997,78.004 ; 122.934,88.072 122.997,88.072 ; 122.997,59.86 123.142,59.86 123.142,60.132 ; 122.997,59.86 122.997,60.132 ; 122.997,60.132 122.997,60.64 ; 122.997,60.132 123.142,60.132 ; 122.997,60.64 123.142,60.64 ; 122.997,60.64 122.997,60.947 ; 122.997,60.947 123.004,60.947 123.142,60.809 123.142,60.64 ; 122.997,70.405 122.997,70.8 ; 122.997,70.8 123.161,70.8 ; 122.997,70.8 122.997,71.308 ; 122.997,71.308 122.997,71.816 ; 122.997,71.308 123.163,71.308 ; 122.997,71.816 122.997,72.324 ; 122.997,71.816 123.165,71.816 ; 122.997,72.324 122.997,72.832 ; 122.997,72.324 123.168,72.324 ; 122.997,72.832 122.997,73.34 ; 122.997,72.832 123.17,72.832 ; 122.997,73.34 122.997,73.848 ; 122.997,73.34 123.173,73.34 ; 122.997,73.848 122.997,74.356 ; 122.997,73.848 123.175,73.848 ; 122.997,74.356 122.997,74.864 ; 122.997,74.356 123.178,74.356 ; 122.997,74.864 122.997,75.372 ; 122.997,74.864 123.175,74.864 ; 122.997,75.372 122.997,75.88 ; 122.997,75.372 123.184,75.372 ; 122.997,75.88 122.997,76.134 122.997,76.388 ; 122.997,75.88 123.505,75.88 ; 122.997,76.388 122.997,76.896 ; 122.997,76.388 123.168,76.388 ; 122.997,76.896 122.997,77.404 ; 122.997,76.896 123.165,76.896 ; 122.997,77.404 122.997,77.912 ; 122.997,77.404 123.163,77.404 ; 122.997,77.912 123.058,77.912 ; 122.997,77.912 122.997,78.004 ; 122.997,78.004 ccw(c123.632,78.361) 123.058,77.912 ; 122.997,78.004 ccw(c123.632,78.361) 123.058,77.912 ; 122.997,88.072 122.997,88.58 ; 122.997,88.072 123.505,88.072 ; 122.997,88.58 122.997,89.088 ; 122.997,88.58 C19.2@123.505,88.58 ; 122.997,89.088 C19.2@123.505,89.088 ; 122.997,95.021 122.997,95.184 ; 122.997,95.021 123.454,95.021 123.505,95.071 ; 122.997,95.184 123.505,95.184 ; 122.997,95.184 122.997,95.692 ; 122.997,95.692 pad.@123.505,95.692 ; 122.997,95.692 122.997,95.946 ; 122.997,95.946 123.505,95.946 ; 123.058,77.912 ccw(c123.632,78.361) 123.117,77.846 cw(c123.632,78.361) 123.058,77.912 ; 123.142,60.132 123.142,60.64 ; 123.168,76.388 ccw(c123.887,76.606) 123.168,76.386 ccw(c123.887,76.606) 123.326,76.106 ccw(c123.887,76.606) 123.328,76.103 ccw(c123.887,76.606) 123.505,75.959 ; 123.175,74.864 cw(c123.887,75.106) 123.184,75.372 ; 123.184,75.372 cw(c123.887,75.106) 123.185,75.375 cw(c123.887,75.106) 123.326,75.606 ; 123.326,75.606 cw(c123.887,75.106) 123.5,75.75 cw(c123.887,75.106) 123.505,75.753 ; 123.356,87.564 cw(c122.601,86.935) 123.373,87.542 ; 123.356,87.564 123.505,87.564 ; 123.373,87.542 123.505,87.542 ; 123.41,58.1 123.505,58.1 ; 123.41,58.1 123.41,58.608 ; 123.41,58.1 123.41,57.713 123.505,57.713 ; 123.41,58.608 123.505,58.608 ; 123.41,58.608 123.41,59.116 ; 123.41,59.116 123.505,59.116 ; 123.41,59.116 123.41,59.515 123.505,59.515 ; 123.505,57.713 124.013,57.713 ; 123.505,57.713 123.505,58.1 ; 123.505,58.1 123.505,58.608 ; 123.505,58.1 C35.1@124.013,58.1 ; 123.505,58.608 123.505,59.116 ; 123.505,58.608 C35.1@124.013,58.608 ; 123.505,59.116 123.505,59.515 ; 123.505,59.116 C35.1@124.013,59.116 ; 123.505,59.515 123.741,59.515 124.013,59.515 ; 123.505,75.753 cw(c123.887,75.106) 123.835,75.856 cw(c123.887,76.606) 123.693,75.88 ; 123.505,75.753 123.505,75.88 ; 123.505,75.88 123.693,75.88 ; 123.505,75.88 123.505,75.959 ; 123.505,75.959 ccw(c123.887,76.606) 123.693,75.88 ; 123.505,87.542 123.505,87.564 ; 123.505,87.542 124.013,87.542 ; 123.505,87.564 123.505,88.072 ; 123.505,87.564 124.013,87.564 ; 123.505,88.072 C19.2@123.505,88.58 ; 123.505,88.072 124.013,88.072 ; C19.2@123.505,88.58 C19.2@124.013,88.58 ; C19.2@123.505,88.58 C19.2@123.505,89.088 ; C19.2@123.505,89.088 123.505,89.596 ; C19.2@123.505,89.088 C19.2@124.013,89.088 ; 123.505,89.596 124.013,89.596 ; 123.505,95.071 123.505,95.184 ; 123.505,95.071 123.618,95.184 ; 123.505,95.184 123.618,95.184 ; 123.505,95.184 pad.@123.505,95.692 ; pad.@123.505,95.692 123.505,95.946 ; pad.@123.505,95.692 pad.@124.013,95.692 ; 123.505,95.946 124.013,95.946 ; 123.618,95.184 123.907,95.474 pad.@124.013,95.579 ; 123.678,69.784 cw(c122.937,69.656) 123.689,69.656 123.689,69.276 ; 123.678,69.784 124.013,69.784 ; 123.689,68.768 123.689,69.276 ; 123.689,68.768 124.013,68.768 ; 123.689,69.276 124.013,69.276 ; 123.977,64.704 124.013,64.704 ; 123.977,64.704 124.013,64.668 ; 124.013,57.713 124.521,57.713 ; 124.013,57.713 C35.1@124.013,58.1 ; C35.1@124.013,58.1 C35.1@124.521,58.1 ; C35.1@124.013,58.1 C35.1@124.013,58.608 ; C35.1@124.013,58.608 C35.1@124.521,58.608 ; C35.1@124.013,58.608 C35.1@124.013,59.116 ; C35.1@124.013,59.116 124.013,59.243 124.013,59.515 ; C35.1@124.013,59.116 124.14,59.116 C35.1@124.521,59.116 ; 124.013,59.515 124.517,59.515 ; 124.013,64.668 124.013,64.704 ; 124.013,64.668 124.173,64.508 124.521,64.508 ; 124.013,64.704 124.521,64.704 ; 124.013,64.704 124.013,64.946 ; 124.013,64.946 ccw(c123.911,65.923) 124.521,65.153 ; 124.013,68.423 cw(c123.73,67.752) 124.026,68.418 ccw(c123.73,67.752) 124.013,68.423 ; 124.013,68.423 ccw(c123.73,67.752) 123.73,68.481 cw(c123.73,67.752) 124.013,68.423 ; 124.013,68.423 124.013,68.768 ; 124.013,68.768 124.013,69.276 ; 124.013,68.768 124.173,68.768 ; 124.013,69.276 124.013,69.784 ; 124.013,69.276 124.521,69.276 ; 124.013,69.784 124.521,69.784 ; 124.013,69.784 124.013,69.854 ; 124.013,69.854 124.521,69.854 ; 124.013,87.542 124.013,87.564 ; 124.013,87.542 124.326,87.542 cw(c125.249,87.205) 124.334,87.564 ; 124.013,87.564 124.013,88.072 ; 124.013,87.564 124.334,87.564 ; 124.013,88.072 C19.2@124.013,88.58 ; 124.013,88.072 124.521,88.072 ; C19.2@124.013,88.58 C19.2@124.521,88.58 ; C19.2@124.013,88.58 C19.2@124.013,89.088 ; C19.2@124.013,89.088 124.013,89.596 ; C19.2@124.013,89.088 C19.2@124.521,89.088 ; 124.013,89.596 pad.@124.521,89.596 ; 124.013,89.596 124.013,90.104 ; 124.013,90.104 pad.@124.521,90.104 ; 124.013,90.104 124.013,90.198 ; 124.013,90.198 124.521,90.198 ; pad.@124.013,95.579 pad.@124.126,95.692 ; pad.@124.013,95.579 pad.@124.013,95.692 ; pad.@124.013,95.692 124.013,95.946 ; pad.@124.013,95.692 pad.@124.126,95.692 ; 124.013,95.946 124.173,95.946 124.173,95.74 pad.@124.126,95.692 ; 124.173,68.768 cw(c124.994,68.228) 124.518,69.088 cw(c124.994,68.228) 124.521,69.09 ; 124.334,87.564 cw(c125.249,87.205) 124.521,87.865 ; 124.517,59.515 ccw(c125.029,60.132) 124.521,59.512 ; 124.517,59.515 ccw(c125.029,60.132) 124.521,59.512 ; 124.517,59.515 cw(c125.029,60.132) 124.514,59.518 ccw(c125.029,60.132) 124.517,59.515 ; 124.521,57.713 125.029,57.713 ; 124.521,57.713 C35.1@124.521,58.1 ; C35.1@124.521,58.1 C35.1@125.029,58.1 ; C35.1@124.521,58.1 C35.1@124.521,58.608 ; C35.1@124.521,58.608 C35.1@124.648,58.608 C35.1@125.029,58.608 ; C35.1@124.521,58.608 124.521,58.735 C35.1@124.521,59.116 ; C35.1@124.521,59.116 C35.1@125.029,59.116 ; C35.1@124.521,59.116 124.521,59.512 ; 124.521,59.512 ccw(c125.029,60.132) 125.029,59.33 ; 124.521,59.512 ccw(c125.029,60.132) 125.029,59.33 ; 124.521,64.508 125.029,64.508 ; 124.521,64.508 124.521,64.704 ; 124.521,64.704 125.029,64.704 ; 124.521,64.704 124.521,65.153 ; 124.521,65.153 ccw(c123.911,65.923) 124.589,65.212 ; 124.521,69.09 124.521,69.276 ; 124.521,69.276 124.521,69.784 ; 124.521,69.276 125.029,69.276 ; 124.521,69.784 124.521,69.854 ; 124.521,69.784 125.029,69.784 ; 124.521,69.854 125.029,69.854 ; 124.521,87.865 cw(c125.249,87.205) 124.786,88.072 ; 124.521,87.865 124.521,88.072 ; 124.521,88.072 C19.2@124.521,88.58 ; 124.521,88.072 124.786,88.072 ; C19.2@124.521,88.58 124.922,88.58 ; C19.2@124.521,88.58 C19.2@124.521,89.088 ; C19.2@124.521,89.088 pad.@124.521,89.596 ; C19.2@124.521,89.088 124.922,89.088 ; pad.@124.521,89.596 124.922,89.596 ; pad.@124.521,89.596 pad.@124.521,90.104 ; pad.@124.521,90.104 124.521,90.198 ; pad.@124.521,90.104 125.029,90.104 ; 124.521,90.198 125.029,90.198 ; 124.589,65.212 ccw(c123.911,65.923) pad.@124.872,65.72 ; 124.589,65.212 125.029,65.212 ; 124.786,88.072 cw(c125.249,87.205) 124.922,88.132 ; pad.@124.872,65.72 pad.@125.029,65.72 ; 124.922,88.132 124.922,88.58 ; 124.922,88.58 124.922,89.088 ; 124.922,89.088 124.922,89.596 ; 124.922,89.596 124.922,89.978 125.029,89.978 ; pad.@125.028,66.094 cw(c124.513,66.609) 124.888,65.984 ccw(c124.513,66.609) pad.@125.028,66.094 ; pad.@125.028,66.094 pad.@125.029,66.095 ; 125.029,57.713 C35.1@125.029,58.1 ; C35.1@125.029,58.1 125.029,58.227 C35.1@125.029,58.608 ; C35.1@125.029,58.1 125.537,58.1 ; C35.1@125.029,58.608 125.537,58.608 ; C35.1@125.029,58.608 C35.1@125.029,59.116 ; C35.1@125.029,59.116 125.537,59.116 ; C35.1@125.029,59.116 125.029,59.33 ; 125.029,59.33 125.332,59.33 125.351,59.311 125.537,59.125 ; 125.029,64.508 125.029,64.704 ; 125.029,64.508 125.43,64.508 125.537,64.615 ; 125.029,64.704 125.537,64.704 ; 125.029,64.704 125.029,65.212 ; 125.029,65.212 125.537,65.212 ; 125.029,65.212 pad.@125.029,65.72 ; pad.@125.029,65.72 pad.@125.029,66.095 ; pad.@125.029,65.72 125.537,65.72 ; pad.@125.029,66.095 125.162,66.228 ; 125.029,69.276 125.029,69.784 ; 125.029,69.276 125.537,69.276 ; 125.029,69.276 125.029,69.21 cw(c124.994,68.228) 125.537,69.047 ; 125.029,69.784 125.029,69.854 ; 125.029,69.784 125.537,69.784 ; 125.029,69.854 125.537,69.854 ; 125.029,89.978 125.029,90.104 ; 125.029,89.978 125.457,89.978 ; 125.029,90.104 125.029,90.198 ; 125.029,90.104 125.491,90.104 ; 125.162,66.228 125.537,66.228 ; 125.162,66.228 125.509,66.575 ; 125.457,89.978 ccw(c126.174,89.85) 125.457,89.977 cw(c126.174,89.85) 125.457,89.978 ; 125.457,89.978 cw(c126.174,89.85) 125.491,90.104 ; 125.457,89.978 cw(c126.174,89.85) 125.491,90.104 ; 125.491,90.104 cw(c126.174,89.85) 125.531,90.192 ccw(c126.174,89.85) 125.491,90.104 ; 125.509,66.575 ccw(c124.994,67.09) 125.537,66.604 ; 125.509,66.575 ccw(c124.994,67.09) 125.537,66.604 ; 125.537,57.713 125.537,58.1 ; 125.537,57.713 125.751,57.713 125.751,58.1 ; 125.537,58.1 125.537,58.608 ; 125.537,58.1 125.751,58.1 ; 125.537,58.608 125.537,59.116 ; 125.537,58.608 125.751,58.608 ; 125.537,59.116 125.537,59.125 ; 125.537,59.116 125.546,59.116 ; 125.537,59.125 125.546,59.116 ; 125.537,64.615 125.626,64.704 ; 125.537,64.615 125.537,64.704 ; 125.537,64.704 125.537,65.212 ; 125.537,64.704 125.626,64.704 ; 125.537,65.212 125.537,65.72 ; 125.537,65.212 126.045,65.212 ; 125.537,65.72 126.045,65.72 ; 125.537,65.72 125.537,66.228 ; 125.537,66.228 126.045,66.228 ; 125.537,66.228 125.537,66.604 ; 125.537,66.604 ccw(c124.994,67.09) 125.631,66.736 ; 125.537,66.604 ccw(c124.994,67.09) 125.631,66.736 ; 125.537,69.047 cw(c124.994,68.228) 125.543,69.043 cw(c124.994,68.228) 125.815,68.768 ; 125.537,69.047 125.537,69.276 ; 125.537,69.276 126.045,69.276 ; 125.537,69.276 125.537,69.784 ; 125.537,69.784 126.045,69.784 ; 125.537,69.784 125.537,69.854 ; 125.537,69.854 126.045,69.854 ; 125.546,59.116 125.751,58.911 125.751,58.608 ; 125.626,64.704 126.045,65.123 ; 125.631,66.736 ccw(c124.994,67.09) 125.722,67.09 ; 125.631,66.736 ccw(c124.994,67.09) 125.722,67.09 ; 125.631,66.736 126.045,66.736 ; 125.722,67.09 125.722,67.244 ; 125.722,67.244 126.045,67.244 ; 125.751,58.1 125.751,58.608 ; 125.815,68.768 cw(c124.994,68.228) pad.@125.976,68.26 ; 125.815,68.768 pad.@126.045,68.768 ; 125.853,67.752 ccw(c124.994,68.228) pad.@125.976,68.26 ; 125.853,67.752 126.045,67.752 ; pad.@125.976,68.26 pad.@126.045,68.26 ; 126.045,65.123 126.045,65.212 ; 126.045,65.123 126.134,65.212 ; 126.045,65.212 126.045,65.72 ; 126.045,65.212 126.134,65.212 ; 126.045,65.72 126.045,66.228 ; 126.045,65.72 126.172,65.72 ; 126.045,66.228 126.172,66.228 ; 126.045,66.228 126.045,66.736 ; 126.045,66.736 126.045,67.244 ; 126.045,66.736 126.172,66.736 ; 126.045,67.244 126.045,67.752 ; 126.045,67.244 126.172,67.244 ; 126.045,67.752 pad.@126.045,68.26 ; 126.045,67.752 126.172,67.752 ; pad.@126.045,68.26 pad.@126.299,68.26 ; pad.@126.045,68.26 pad.@126.045,68.768 ; pad.@126.045,68.768 126.045,69.276 ; pad.@126.045,68.768 126.553,68.768 ; 126.045,69.276 126.045,69.784 ; 126.045,69.276 126.553,69.276 ; 126.045,69.784 126.553,69.784 ; 126.045,69.784 126.045,69.854 ; 126.134,65.212 126.172,65.25 ; 126.172,65.25 126.172,65.72 ; 126.172,65.25 126.533,65.611 126.172,65.25 ; 126.172,65.72 126.553,65.72 ; 126.172,65.72 126.172,66.228 ; 126.172,66.228 126.553,66.228 ; 126.172,66.228 126.172,66.736 ; 126.172,66.736 126.172,67.244 ; 126.172,66.736 126.553,66.736 ; 126.172,67.244 126.172,67.752 ; 126.172,67.244 126.553,67.244 ; 126.172,67.752 126.553,67.752 ; 126.172,67.752 126.172,68.133 pad.@126.299,68.26 ; pad.@126.299,68.26 pad.@126.553,68.26 ; pad.@126.299,68.26 pad.@126.553,68.514 ; 126.553,65.72 126.553,66.228 ; 126.553,66.228 pad.@126.807,66.228 ; 126.553,66.228 126.553,66.736 ; 126.553,66.736 126.553,67.244 ; 126.553,66.736 pad.@126.807,66.736 ; 126.553,67.244 126.553,67.752 ; 126.553,67.244 126.807,67.244 ; 126.553,67.752 pad.@126.553,68.26 ; 126.553,67.752 126.807,67.752 ; pad.@126.553,68.26 126.807,68.26 ; pad.@126.553,68.26 pad.@126.553,68.514 ; pad.@126.553,68.514 126.553,68.768 ; pad.@126.553,68.514 126.807,68.768 ; 126.553,68.768 126.553,69.276 ; 126.553,68.768 126.807,68.768 ; 126.553,69.276 126.553,69.784 ; 126.553,69.276 126.807,69.276 ; 126.553,69.784 126.807,69.784 ; 126.553,69.784 126.553,69.877 ; 126.553,69.877 126.807,69.877 126.807,69.784 ; pad.@126.807,66.228 126.807,65.885 126.535,65.613 127.061,66.139 ; pad.@126.807,66.228 pad.@127.061,66.228 ; pad.@126.807,66.228 pad.@126.807,66.736 ; pad.@126.807,66.736 126.807,67.244 ; pad.@126.807,66.736 pad.@127.061,66.736 ; 126.807,67.244 126.807,67.752 ; 126.807,67.244 127.061,67.244 ; 126.807,67.752 126.807,68.26 ; 126.807,67.752 127.061,67.752 ; 126.807,68.26 126.807,68.768 ; 126.807,68.26 127.061,68.26 ; 126.807,68.768 126.807,69.133 126.807,69.276 ; 126.807,68.768 126.934,68.895 127.045,68.895 127.061,68.895 ; 126.807,68.768 127.061,68.768 ; 126.807,69.276 126.807,69.784 ; 127.061,66.139 pad.@127.061,66.228 ; 127.061,66.139 pad.@127.15,66.228 ; pad.@127.061,66.228 pad.@127.15,66.228 ; pad.@127.061,66.228 pad.@127.061,66.736 ; pad.@127.061,66.736 127.569,66.736 ; pad.@127.061,66.736 127.061,67.244 ; 127.061,67.244 127.061,67.752 ; 127.061,67.244 127.569,67.244 ; 127.061,67.752 127.061,68.26 ; 127.061,67.752 127.569,67.752 ; 127.061,68.26 127.061,68.768 ; 127.061,68.26 127.569,68.26 ; 127.061,68.768 127.061,68.879 127.061,68.895 ; 127.061,68.768 127.569,68.768 ; 127.061,68.895 127.569,68.895 ; 127.569,66.647 127.658,66.736 ; 127.569,66.647 127.569,66.736 ; 127.569,66.736 127.658,66.736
